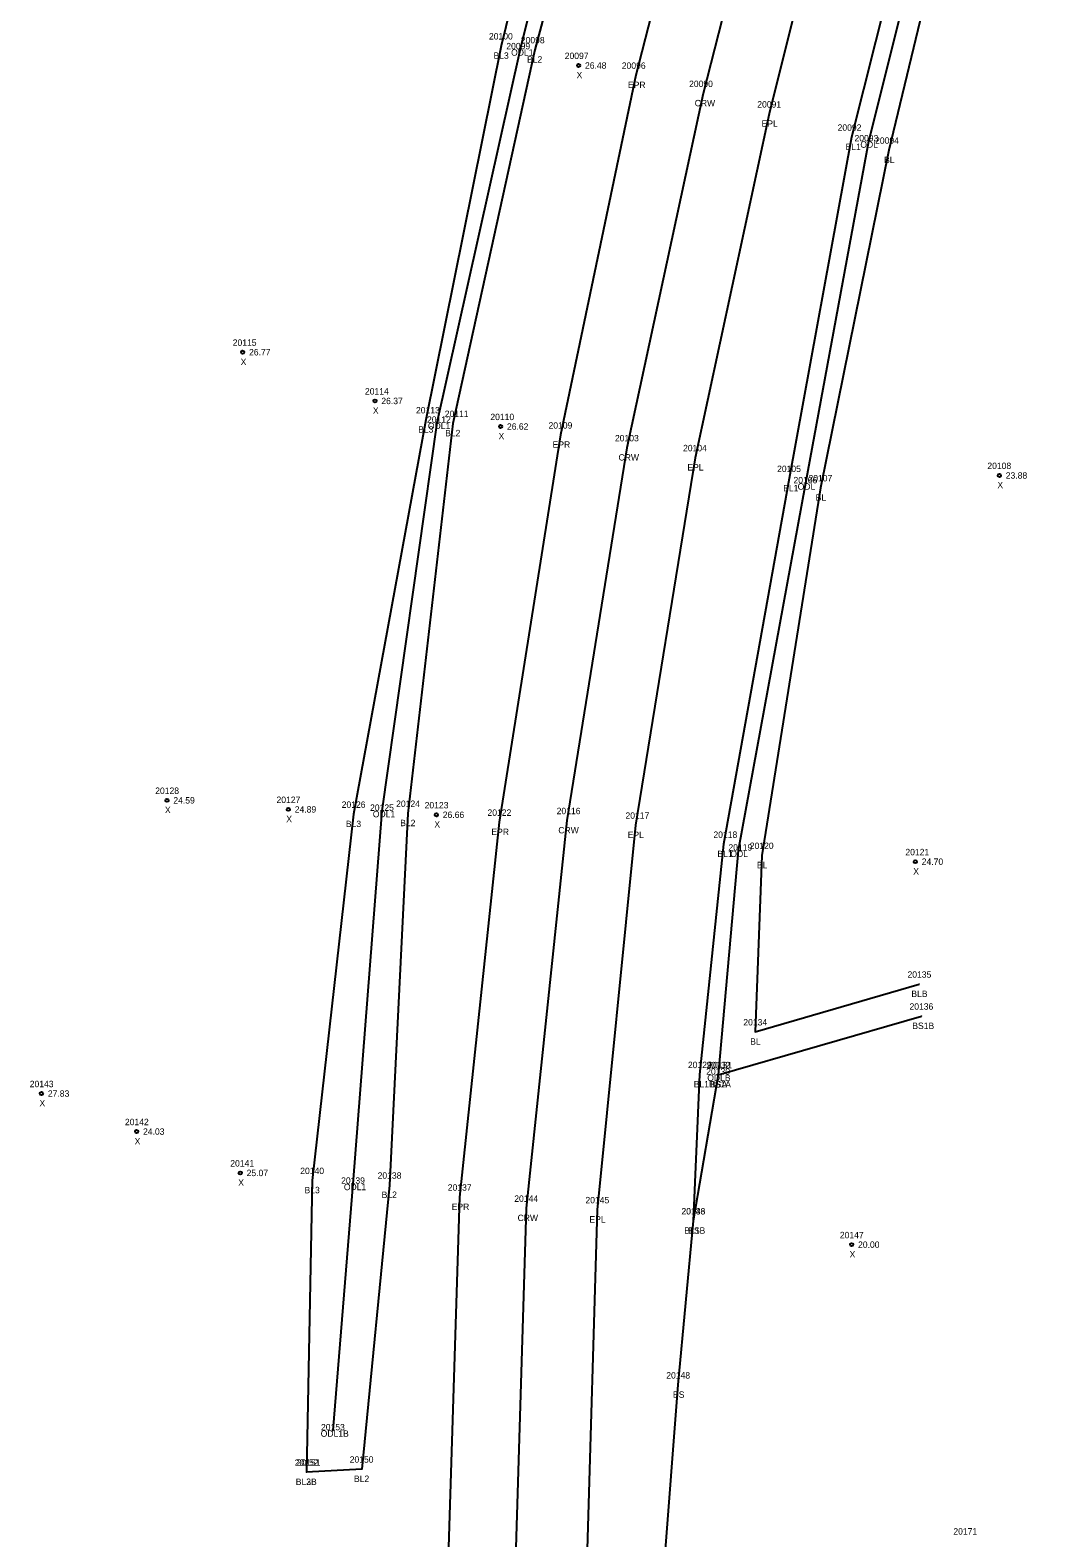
# Model space of a CAD drawing. Extents: x 2432729 to 2433340, y 684958 to 688103.
# Drawn here: x 2432848.6 to 2433007.3, y 687162.2 to 687397.5 of the extents above; entities that cross this region are included whole.
import ezdxf

# ---------------------------------------------------------------- set-up
doc = ezdxf.new("R2010")
doc.units = 0
for name, color, linetype in [('RD_DTM_BkLn1', 7, 'Continuous'), ('RD_DTM_BkLn2', 7, 'Continuous'), ('RD_EX_H2O', 7, 'Continuous'), ('RD_EX_H2O_txCode', 7, 'Continuous'), ('RD_EX_Road', 7, 'Continuous'), ('RD_EX_Road_txCode', 7, 'Continuous'), ('RD_Sketch8', 7, 'Continuous'), ('RD_SMD_Locator', 7, 'Continuous'), ('RD_SMD_Misc', 7, 'Continuous')]:
    doc.layers.add(name, color=color, linetype=linetype)

msp = doc.modelspace()

# ---------------------------------------------------------------- linework, layer by layer
at = {"layer": 'RD_DTM_BkLn1'}
for points in [[(2433118.26, 688093.2), (2433092.06, 687992.21), (2433063.59, 687892.57), (2433035.4, 687792.67), (2433003.26, 687693.63), (2432973.78, 687591.87), (2432942.45, 687477.63), (2432922.14, 687395), (2432910.39, 687336.67), (2432899.1, 687275.13), (2432892.65, 687218), (2432891.75, 687172.49)], [(2433125.46, 688091.48), (2433098.1, 687989.98), (2433070.67, 687890.07), (2433044.57, 687790.6), (2433009.89, 687691.98), (2432980.82, 687589.28), (2432951.34, 687483.95), (2432927.37, 687394.4), (2432914.6, 687336.1), (2432907.58, 687275.27), (2432904.68, 687217.27), (2432900.37, 687172.96), (2432891.75, 687172.49)], [(2433140.82, 688087.65), (2433112.94, 687984.39), (2433086.23, 687884.97), (2433060.15, 687787.81), (2433032.83, 687687.07), (2433004.93, 687584.9), (2432976.21, 687475.71), (2432953.67, 687387.58), (2432941.78, 687332.31), (2432932.37, 687274.14), (2432926.02, 687213.66), (2432924.35, 687158.94)], [(2433156.54, 688084.3), (2433128.42, 687980.72), (2433101.84, 687880.23), (2433076.15, 687783.58), (2433056.79, 687706.65), (2433053.61, 687680.85), (2433043.6, 687649.71), (2433027.96, 687578.58), (2432999.4, 687470.47), (2432976.82, 687380.76), (2432967.08, 687327.52), (2432956.82, 687270.44), (2432953.12, 687234.52), (2432952.13, 687211.69)], [(2433161.14, 688083.06), (2433133.45, 687979.3), (2433106.44, 687878.75), (2433080.34, 687782.58), (2433063.71, 687704.97), (2433062.78, 687678.91), (2433051.75, 687646.46), (2433035.42, 687577.73), (2433004.6, 687469.86), (2432982.67, 687378.73), (2432971.98, 687326.06), (2432962.83, 687268.71), (2432961.78, 687241.18), (2432987.4, 687248.62)]]:
    msp.add_lwpolyline(points, dxfattribs=at)
at = {"layer": 'RD_DTM_BkLn2'}
msp.add_line((2432956.03, 687234.5), (2432987.74, 687243.63), dxfattribs=at)
msp.add_lwpolyline([(2432956.03, 687234.5), (2432952.13, 687211.69), (2432949.74, 687186.09), (2432947.53, 687157.65), (2432946.61, 687110.22), (2432949.21, 687089.9), (2432959.59, 687041.68)], dxfattribs=at)
at = {"layer": 'RD_EX_H2O'}
for points in [[(2433122.48, 688092.22), (2433094.03, 687991.07), (2433066.93, 687892.02), (2433040.1, 687791.41), (2433006.23, 687692.29), (2432977.32, 687590.19), (2432946.52, 687480.52), (2432925.1, 687394.47), (2432912.11, 687336.21), (2432903.51, 687275.66), (2432898.99, 687217.48), (2432895.84, 687179.01)], [(2433158.82, 688083.82), (2433130.6, 687980.05), (2433103.89, 687879.65), (2433077.93, 687783.05), (2433058.91, 687706.24), (2433056.32, 687679.85), (2433046.3, 687648.55), (2433031.84, 687578.12), (2433002.04, 687470.32), (2432979.46, 687380.11), (2432969.67, 687326.76), (2432959.16, 687269.46), (2432956.03, 687234.5)]]:
    msp.add_lwpolyline(points, dxfattribs=at)
at = {"layer": 'RD_EX_Road'}
for points in [[(2433130.63, 688090.22), (2433103.18, 687988.73), (2433075.68, 687887.89), (2433049.83, 687790.75), (2433022.33, 687689.17), (2432994.76, 687586.82), (2432966.23, 687480.17), (2432943.15, 687390.42), (2432931.4, 687334.3), (2432921.83, 687273.88), (2432915.64, 687215.4), (2432913.86, 687159.12)], [(2433151.11, 688085.43), (2433123.35, 687982.08), (2433096.36, 687882.07), (2433070.62, 687785.25), (2433042.64, 687684.31), (2433015.24, 687582.49), (2432986.34, 687474.01), (2432964, 687384.38), (2432952.4, 687330.76), (2432943.09, 687273.42), (2432937.12, 687213.43), (2432935.51, 687158.7)]]:
    msp.add_lwpolyline(points, dxfattribs=at)
at = {"layer": 'RD_SMD_Locator'}
for centre, radius in [((2432922.14, 687395), 0.001), ((2432925.1, 687394.47), 0.001), ((2432927.37, 687394.4), 0.001), ((2432934.22, 687391.95), 0.25), ((2432943.15, 687390.42), 0.001), ((2432953.67, 687387.58), 0.001), ((2432964, 687384.38), 0.001), ((2432976.82, 687380.76), 0.001), ((2432979.46, 687380.11), 0.001), ((2432982.67, 687378.73), 0.001), ((2432881.78, 687347.21), 0.25), ((2432902.43, 687339.61), 0.25), ((2432910.39, 687336.67), 0.001), ((2432912.11, 687336.21), 0.001), ((2432914.6, 687336.1), 0.001), ((2432922.04, 687335.62), 0.25), ((2432931.4, 687334.3), 0.001), ((2432941.78, 687332.31), 0.001), ((2432952.4, 687330.76), 0.001), ((2432967.08, 687327.52), 0.001), ((2432969.67, 687326.76), 0.001), ((2432971.98, 687326.06), 0.001), ((2432999.91, 687327.99), 0.25), ((2432869.96, 687277.3), 0.25), ((2432888.91, 687275.89), 0.25), ((2432899.1, 687275.13), 0.001), ((2432903.51, 687275.66), 0.001), ((2432907.58, 687275.27), 0.001), ((2432912.02, 687275.05), 0.25), ((2432921.83, 687273.88), 0.001), ((2432932.37, 687274.14), 0.001), ((2432943.09, 687273.42), 0.001), ((2432956.82, 687270.44), 0.001), ((2432959.16, 687269.46), 0.001), ((2432962.83, 687268.71), 0.001), ((2432986.79, 687267.73), 0.25), ((2432987.4, 687248.62), 0.001), ((2432987.74, 687243.63), 0.001), ((2432961.78, 687241.18), 0.001), ((2432953.12, 687234.52), 0.001), ((2432956.03, 687234.5), 0.001), ((2432956.03, 687234.5), 0.001), ((2432956.03, 687234.5), 0.001), ((2432850.37, 687231.55), 0.25), ((2432865.23, 687225.62), 0.25), ((2432881.4, 687219.17), 0.25), ((2432892.65, 687218), 0.001), ((2432898.99, 687217.48), 0.001), ((2432904.68, 687217.27), 0.001), ((2432915.64, 687215.4), 0.001), ((2432926.02, 687213.66), 0.001), ((2432937.12, 687213.43), 0.001), ((2432952.13, 687211.69), 0.001), ((2432952.13, 687211.69), 0.001), ((2432976.85, 687207.98), 0.25), ((2432949.74, 687186.09), 0.001), ((2432895.84, 687179.01), 0.001), ((2432891.75, 687172.49), 0.001), ((2432891.75, 687172.49), 0.001), ((2432900.37, 687172.96), 0.001)]:
    msp.add_circle(centre, radius, dxfattribs=at)

# ---------------------------------------------------------------- texts
at = {"layer": 'RD_EX_H2O_txCode'}
for s, p in [('20099', (2432922.94, 687394.47)), ('ODL1', (2432923.69, 687393.47)), ('20093', (2432977.3, 687380.11)), ('ODL', (2432978.21, 687379.11)), ('20112', (2432910.56, 687336.21)), ('ODL1', (2432910.7, 687335.21)), ('20106', (2432967.77, 687326.76)), ('ODL', (2432968.42, 687325.76)), ('20125', (2432901.67, 687275.66)), ('ODL1', (2432902.1, 687274.66)), ('20119', (2432957.61, 687269.46)), ('ODL', (2432957.92, 687268.46)), ('20130', (2432954.15, 687234.5)), ('ODLB', (2432954.31, 687233.5)), ('20139', (2432897.15, 687217.48)), ('ODL1', (2432897.58, 687216.48)), ('ODL1B', (2432893.96, 687178.01)), ('20153', (2432894.01, 687179.01))]:
    msp.add_text(s, height=1, dxfattribs=at).set_placement(p)
at = {"layer": 'RD_EX_Road_txCode'}
for s, p in [('20096', (2432940.97, 687391.42)), ('EPR', (2432941.93, 687388.42)), ('20091', (2432962.12, 687385.38)), ('EPL', (2432962.79, 687382.38)), ('20109', (2432929.53, 687335.3)), ('EPR', (2432930.17, 687332.3)), ('20104', (2432950.53, 687331.76)), ('EPL', (2432951.2, 687328.76)), ('20122', (2432920, 687274.88)), ('20117', (2432941.54, 687274.42)), ('EPR', (2432920.61, 687271.88)), ('EPL', (2432941.89, 687271.42)), ('20137', (2432913.8, 687216.4)), ('20145', (2432935.29, 687214.43)), ('EPR', (2432914.41, 687213.4)), ('EPL', (2432935.92, 687211.43))]:
    msp.add_text(s, height=1, dxfattribs=at).set_placement(p)
at = {"layer": 'RD_Sketch8'}
for s, p in [('20097', (2432932.06, 687392.95)), ('26.48', (2432935.22, 687391.45)), ('X', (2432933.91, 687389.95)), ('20115', (2432880.23, 687348.21)), ('26.77', (2432882.78, 687346.71)), ('X', (2432881.47, 687345.21)), ('20114', (2432900.87, 687340.61)), ('26.37', (2432903.43, 687339.11)), ('X', (2432902.11, 687337.61)), ('20110', (2432920.45, 687336.62)), ('26.62', (2432923.04, 687335.12)), ('X', (2432921.73, 687333.62)), ('20108', (2432998.04, 687328.99)), ('23.88', (2433000.91, 687327.49)), ('X', (2432999.6, 687325.99)), ('20128', (2432868.13, 687278.3)), ('24.59', (2432870.96, 687276.8)), ('20127', (2432887.07, 687276.89)), ('20123', (2432910.19, 687276.05)), ('X', (2432869.65, 687275.3)), ('X', (2432888.59, 687273.89)), ('24.89', (2432889.91, 687275.39)), ('26.66', (2432913.02, 687274.55)), ('X', (2432911.71, 687273.05)), ('20121', (2432985.24, 687268.73)), ('24.70', (2432987.79, 687267.23)), ('X', (2432986.47, 687265.73)), ('20143', (2432848.54, 687232.55)), ('27.83', (2432851.37, 687231.05)), ('X', (2432850.06, 687229.55)), ('20142', (2432863.4, 687226.62)), ('24.03', (2432866.23, 687225.12)), ('X', (2432864.92, 687223.62)), ('20141', (2432879.85, 687220.17)), ('X', (2432881.09, 687217.17)), ('25.07', (2432882.4, 687218.67)), ('20147', (2432975.01, 687208.98)), ('20.00', (2432977.85, 687207.48)), ('X', (2432976.53, 687205.98))]:
    msp.add_text(s, height=1, dxfattribs=at).set_placement(p)
at = {"layer": 'RD_SMD_Misc'}
for s, p in [('20100', (2432920.23, 687396)), ('20098', (2432925.21, 687395.4)), ('BL3', (2432920.94, 687393)), ('BL2', (2432926.17, 687392.4)), ('20090', (2432951.47, 687388.58)), ('CRW', (2432952.35, 687385.58)), ('20092', (2432974.66, 687381.76)), ('20094', (2432980.51, 687379.73)), ('BL1', (2432975.9, 687378.76)), ('BL', (2432981.91, 687376.73)), ('20113', (2432908.84, 687337.67)), ('20111', (2432913.33, 687337.1)), ('BL3', (2432909.19, 687334.67)), ('BL2', (2432913.39, 687334.1)), ('20103', (2432939.9, 687333.31)), ('CRW', (2432940.46, 687330.31)), ('20105', (2432965.21, 687328.52)), ('BL1', (2432966.16, 687325.52)), ('20107', (2432970.11, 687327.06)), ('BL', (2432971.23, 687324.06)), ('20126', (2432897.24, 687276.13)), ('20124', (2432905.74, 687276.27)), ('BL2', (2432906.37, 687273.27)), ('20116', (2432930.8, 687275.14)), ('BL3', (2432897.89, 687273.13)), ('CRW', (2432931.06, 687272.14)), ('20118', (2432955.27, 687271.44)), ('20120', (2432960.95, 687269.71)), ('BL1', (2432955.9, 687268.44)), ('BL', (2432962.07, 687266.71)), ('20135', (2432985.57, 687249.62)), ('BLB', (2432986.17, 687246.62)), ('20136', (2432985.88, 687244.63)), ('20134', (2432959.94, 687242.18)), ('BS1B', (2432986.32, 687241.63)), ('BL', (2432961.02, 687239.18)), ('20129', (2432951.29, 687235.52)), ('20132', (2432954.19, 687235.5)), ('20131', (2432954.47, 687235.5)), ('BL1', (2432952.2, 687232.52)), ('BS1A', (2432954.59, 687232.5)), ('BSA', (2432954.76, 687232.5)), ('20140', (2432890.77, 687219)), ('20138', (2432902.85, 687218.27)), ('BL3', (2432891.44, 687216)), ('BL2', (2432903.48, 687215.27)), ('20144', (2432924.18, 687214.66)), ('20146', (2432950.27, 687212.69)), ('20133', (2432950.29, 687212.69)), ('CRW', (2432924.7, 687211.66)), ('BL1B', (2432950.73, 687209.69)), ('BS', (2432951.35, 687209.69)), ('20148', (2432947.91, 687187.09)), ('BS', (2432948.96, 687184.09)), ('20152', (2432889.92, 687173.49)), ('20151', (2432890.2, 687173.49)), ('20150', (2432898.49, 687173.96)), ('BL2B', (2432890.07, 687170.49)), ('BL3B', (2432890.07, 687170.49)), ('BL2', (2432899.16, 687170.96)), ('20171', (2432992.73, 687162.75))]:
    msp.add_text(s, height=1, dxfattribs=at).set_placement(p)

doc.saveas('drawing.dxf')
